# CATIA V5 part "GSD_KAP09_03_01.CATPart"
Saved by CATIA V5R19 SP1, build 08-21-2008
Part number: GSD_REPETITION_02
Description: Beispielmodell: Wiederholung von Punkten und Ebenen  Maik Hertha IT Consultants
Bounding box of the stored display mesh (mm): x -80.67 to 90.705, y 0 to 0, z 19.637 to 52.356
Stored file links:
  \GSD_BUCH_UEBUNG\GSD_KAP09_03_01.CATPart
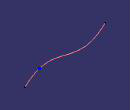
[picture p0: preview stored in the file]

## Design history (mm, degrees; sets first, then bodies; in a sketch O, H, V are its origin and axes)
AxisSystem1: origin (0, 0, 0), X (1, 0, 0), Y (0, 1, 0), Z (0, 0, 1)
Set1
  Sketch1 on ZX plane of AxisSystem1, origin (0, 0, 0), H (0, 0, 1), V (1, 0, 0)
    spline S1 through (19.6367, 90.705) (41.1927, 35.896) (30.0298, -28.9484) (52.3557, -80.6695)
  Point1: type OnCurve, Support Sketch1, Ratio 0.2
Body1 (main body)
